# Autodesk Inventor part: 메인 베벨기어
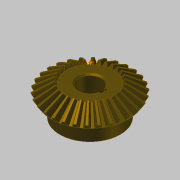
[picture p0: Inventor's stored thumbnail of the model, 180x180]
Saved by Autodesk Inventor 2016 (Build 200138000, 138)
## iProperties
Created: 2014-10
Part Number: 메인 베벨기어
Material: 강철, 탄소
Document SubType Name: Modeling
Designer: KYOUNG IL JANG
Categories: <?xml version="1.0" encoding="UTF-16"?> <MemberInstance><Categories><FamilyTemplate><FamilyTemplateParameter ValueType="xs:double" Id="1" ObjectReferenceKey="da
Mass: 269.926 g
Surface Area: 108.837 cm^2
Volume: 34.2981 cm^3
Density: 7.87 g/cm^3
Appearance: 얼룩무늬
CustomPartVersion: 1
Revision Number: 1
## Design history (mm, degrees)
node "맨 위 점"
node "메쉬 평면2"
sketch "톱니 본체 스케치"
  geometry: L1 (0, 0)-(28.669, -21.997); L2 (28.669, -21.997)-(31.109, -18.336); L3 (31.109, -18.336)-(0, 0); L4 (30, -20)-(0, 0); L5 (17.219, -13.212)-(18.685, -11.013); L6 (28.669, -21.997)-(17.219, -13.212); L7 (31.109, -18.336)-(18.685, -11.013); L8 (0, -39.387)-(0, 6.564) reference; L9 (0, -20)-(31.109, -20)
  constraints: 16 end point, 4 point on line, 3 perpendicular, 2 collinear, 1 horizontal alignment, 1 vertical alignment
  dimensions: "d0" = 60 diameter of L4.start L8 (= da_de); "d1" = 57.33744 diameter of L1.end L8 (= da_dfe); "d2" = 62.2188 diameter of L2.end L8 (= da_dae); "d3" = 14.4 distance between parallel lines of L2 L5 (= da_b); "d4" = 18.3359 vertical distance of L2.end L1.start (= da_ve)
revolve "톱니 본체" sketch "톱니 본체 스케치" stored, may be unused: angle "d5" = 90 deg
node "시작점"
node "톱니 평면"
sketch "시작 스케치"
  geometry: L1 (0, -23.505)-(0, 10.645) reference; L2 (-0.709, -2.928)-(0.709, -2.928); A1 r 19.188 centre (-19.457, -7.014) between (-0.709, -2.928) and (-3.232, 3.229); A2 r 19.188 centre (19.457, -7.014) between (3.232, 3.229) and (0.709, -2.928); A3 r 57.403 centre (0, -54.083) between (3.232, 3.229) and (-3.232, 3.229); 1 further point
  constraints: 6 point on circle, 3 centre point, 3 symmetric about line, 2 end point, 1 coincident, 1 perpendicular, 1 other
  dimensions: "d7" = 19.18795 radius of A1 (= fd_rr); "d8" = 19.45712 horizontal distance of point (0, -54.083) A1.centre (= fd_x); "d9" = 47.06905 vertical distance of point (0, -54.083) A1.centre (= fd_y); "d57" = 57.40327 radius of A3 (= 0.5 x fd_dva + 0.3 x da_he); "d58" = 51.15527 distance from line of A3.centre L2 (= 0.5 x fd_dva - 1.12 x da_he)
node "끝점"
  node "끝 평면"
sketch "3D 스케치 오른쪽"
  node "Helical Curve Right" dims "d65" = 229.90621 (computed from da_dm, da_delta, da_beta), "d66" = 31.5, "d67" = 60 (= da_de), "d68" = -9.82794 (= -da_delta), "d69" = 8.10972 (computed from fd_loft, da_delta)
node "끝 평면 오른쪽"
sketch "끝 스케치 오른쪽"
  geometry: L1 (0, -41.54)-(0, 13.178) reference; L2 (-0.422, -1.69)-(0.422, -1.69); A1 r 11.427 centre (-11.587, -4.123) between (-0.422, -1.69) and (-1.925, 1.977); A2 r 11.427 centre (11.587, -4.123) between (1.925, 1.977) and (0.422, -1.69); A3 r 34.184 centre (0, -32.153) between (1.925, 1.977) and (-1.925, 1.977); 1 further point
  constraints: 6 point on circle, 3 centre point, 3 symmetric about line, 2 end point, 1 coincident, 1 perpendicular, 1 other
  dimensions: "d70" = 11.58699 horizontal distance of A3.centre A1.centre (computed from fd_x, fd_ratio); "d71" = 28.03028 vertical distance of point (0, -32.153) A1.centre (computed from fd_y, fd_ratio); "d72" = 11.4267 radius of A1 (computed from fd_rr, fd_ratio); "d73" = 30.46369 distance from line of point (0, -32.153) L2 (computed from d58, fd_ratio); "d74" = 34.18446 radius of A3 (computed from d57, fd_ratio)
feature "로프트 오른쪽" sketch "끝 스케치 오른쪽" dims "d75" = 0, "d77" = 0, "d79" = 0, "d80" = 90 deg, "d85" = 20, "d92" = 90 deg, "d93" = 90 deg, "da_teethtype" = 0 [user parameter]
sketch "3D 스케치 왼쪽"
  node "Helical Curve Left" dims "d26" = 229.90621 (computed from da_dm, da_delta, da_beta), "d27" = 8.10972 (computed from fd_loft, da_delta), "d28" = 60 (= da_de), "d29" = -9.82794 (= -da_delta)
node "끝 평면 왼쪽"
sketch "끝 스케치 왼쪽" dims "d56" = 10.3728 (derived)
  geometry: L1 (0, -43.753)-(0, 15.405) reference; L2 (-0.422, -1.678)-(0.422, -1.678); A1 r 11.427 centre (-11.587, -4.111) between (-0.422, -1.678) and (-1.925, 1.988); A2 r 11.427 centre (11.587, -4.111) between (1.925, 1.988) and (0.422, -1.678); A3 r 34.184 centre (0, -32.142) between (1.925, 1.988) and (-1.925, 1.988); 2 further points; 1 other entity
  constraints: 6 point on circle, 3 centre point, 3 symmetric about line, 2 end point, 1 coincident, 2 other
  dimensions: "d30" = 11.4267 radius of A1 (computed from fd_rr, fd_ratio); "d31" = 11.58699 horizontal distance of point (0, -32.142) A1.centre (computed from fd_x, fd_ratio); "d32" = 28.03028 vertical distance of A1.centre point (0, -32.142) (computed from fd_y, fd_ratio); "d61" = 34.18446 radius of A3 (computed from d57, fd_ratio); "d62" = 30.46369 distance from line of point (0, -32.142) L2 (computed from d58, fd_ratio)
feature "로프트 왼쪽" sketch "끝 스케치 왼쪽" dims "d35" = 0, "d37" = 0, "d39" = 0, "d40" = 90 deg, "d84" = 10, "d90" = 90 deg, "d91" = 90 deg, "da_teethtype" = 0 [user parameter]
sketch "본체 스케치"
  geometry: L1 (0, -35.038)-(0, -19.531) reference; L2 (28.669, -21.997)-(17.219, -13.212) reference; L3 (17.219, -13.212)-(0, -13.212); L4 (28.669, -21.997)-(0, -21.997)
  constraints: 4 end point, 2 perpendicular, 2 point on line
revolve "본체 고정" sketch "본체 스케치" stored, may be unused: angle "d46" = 90 deg
feature "피치 지름" dims angle "d47" = 90 deg
sketch "스케치8"
  geometry: C1 r 22.5 at (0, 0); 1 further point
  constraints: 1 centre point, 1 coincident
  dimensions: "d94" = 45 diameter of C1
extrude "돌출1" join sketch "스케치8" distance "d95" = 13; taper "d96" = 0 deg
sketch "스케치9"
  geometry: 1 further point
hole "구멍1" sketch "스케치9" at (0, 0) diameter "d97" = 17; stored, may be unused: countersink angle "d101" = 90 deg, drill point angle "d103" = 118 deg; dims "d98" = 6, "d99" = 4, "d100" = 2, "d102" = 8
sketch "스케치10"
  geometry: L1 (8.124, 2.5)-(10.8, 2.5); L2 (10.8, 2.5)-(10.8, -2.5); L3 (10.8, -2.5)-(8.124, -2.5); A1 r 8.5 centre (0, 0) between (8.124, 2.5) and (8.124, -2.5) reference; 1 further point
  constraints: 6 end point, 2 parallel, 2 point on circle, 1 horizontal, 1 perpendicular
  dimensions: "d104" = 5 distance of L1.end L2.end; "d112" = 19.3 dimension on A1 L2
extrude "돌출2" cut sketch "스케치10" stored distance "d106" = 10; taper "d107" = 0 deg
chamfer "모따기1" distance "d108" = 1; stored, may be unused: second distance "d109" = 2, angle "d110" = 45 deg
fillet "모깎기1" dims "d111" = 2
body "Solid1"
feature "로프트" dims "d17" = 0, "d18" = 90 deg, "d19" = 0, "d20" = 90 deg, "d89" = 0, "da_teethtype" = 0 [user parameter]
pattern_circular "원형 패턴" dims angle "d22" = 360 deg, "d88" = 0, "da_teethtype" = 0 [user parameter]
pattern_circular "원형 패턴 오른쪽" dims angle "d82" = 360 deg, "da_teethtype" = 0 [user parameter]
pattern_circular "원형 패턴 왼쪽" dims angle "d42" = 360 deg, "da_teethtype" = 0 [user parameter]
sketch "끝 스케치"
  geometry: L1 (0, -15.359)-(0, 6.983) reference; L2 (-0.422, -1.69)-(0.422, -1.69); A1 r 11.427 centre (-11.587, -4.123) between (-0.422, -1.69) and (-1.925, 1.977); A2 r 11.427 centre (11.587, -4.123) between (1.925, 1.977) and (0.422, -1.69); A3 r 34.184 centre (0, -32.153) between (1.925, 1.977) and (-1.925, 1.977); 1 further point
  constraints: 6 point on circle, 3 centre point, 3 symmetric about line, 2 end point, 1 coincident, 1 other
  dimensions: "d12" = 11.4267 radius of A1 (computed from fd_rr, fd_ratio); "d15" = 11.58699 horizontal distance of A1.centre point (0, -32.153) (computed from fd_x, fd_ratio); "d16" = 28.03028 vertical distance of A1.centre point (0, -32.153) (computed from fd_y, fd_ratio); "d59" = 34.18446 radius of A3 (computed from d57, fd_ratio); "d60" = 30.46369 distance from line of A3.centre L2 (computed from d58, fd_ratio)
sketch "Sketch6"
  geometry: L1 (30, -20)-(0, 0) reference; L2 (0, -37.8)-(0, 6.3) reference
body "Srf1"
other parameters: "da_b" = 14.4 [user parameter; used in 2 equation terms], "da_de" = 60 [user parameter; used in 4 equation terms], "da_dae" = 62.2188 [user parameter; used in 2 equation terms], "da_dfe" = 57.33744 [user parameter; used in 1 equation term], "da_le" = 36.05551 [user parameter; used in 1 equation term], "da_omega" = 90 deg [user parameter; used in 1 equation term], "da_beta" = 0 [user parameter; used in 2 equation terms], "da_delta" = 9.82794 [user parameter; used in 8 equation terms], "da_alpha" = 20 deg [user parameter; used in 2 equation terms], "da_he" = 4.4 [user parameter; used in 4 equation terms], "da_ve" = 18.3359 [user parameter; used in 1 equation term], "fd_dv" = 108.16654 (computed from da_de, da_delta) [user parameter; used in 1 equation term], "fd_dva" = 112.16654 (computed from da_dae, da_delta) [user parameter; used in 3 equation terms], "fd_dvb" = 101.6433 (computed from fd_dv, da_alpha) [user parameter; used in 2 equation terms], "da_zv" = 540.83269 [user parameter; used in 1 equation term], "fd_loft" = 14.62 (= da_b + 0.05 x da_he) [user parameter; used in 4 equation terms], "fd_ratio" = 5.95514 (computed from da_le, fd_loft) [user parameter; used in 15 equation terms], "fd_rr" = 19.18795 (computed from fd_dd, fd_dvb) [user parameter; used in 6 equation terms], "fd_angle" = 0.29367 (computed from da_zv) [user parameter; used in 4 equation terms], "fd_x1" = 1.58802 (computed from da_dvw, fd_angle) [user parameter; used in 1 equation term], "fd_y1" = 54.05995 (computed from da_dvw, fd_angle) [user parameter; used in 1 equation term], "fd_x2" = 17.8691 (computed from fd_rr, fd_angle2, fd_angle) [user parameter; used in 1 equation term], "fd_y2" = 6.9909 (computed from fd_rr, fd_angle2, fd_angle) [user parameter; used in 1 equation term], "fd_x" = 19.45712 (= fd_x1 + fd_x2) [user parameter; used in 4 equation terms], "fd_y" = 47.06905 (= fd_y1 - fd_y2) [user parameter; used in 4 equation terms], "fd_angle2" = 3.43555 (computed from fd_dvb, fd_dd, da_alpha) [user parameter; used in 2 equation terms], "fd_dd" = 108.64654 (= fd_dva - 0.8 x da_he) [user parameter; used in 2 equation terms], "da_dvw" = 108.16654 [user parameter; used in 2 equation terms], "d11" = 14.62 (= fd_loft), "da_dm" = 48.01848 [user parameter; used in 2 equation terms], "da_x" = 0 [user parameter], "da_m" = 2 [user parameter], "d48" = 0, "d49" = 0, "d50" = 90 deg (= da_omega), "d51" = 6 deg (computed from da_z), "d52" = 0, "d53" = 0, "d54" = 0
